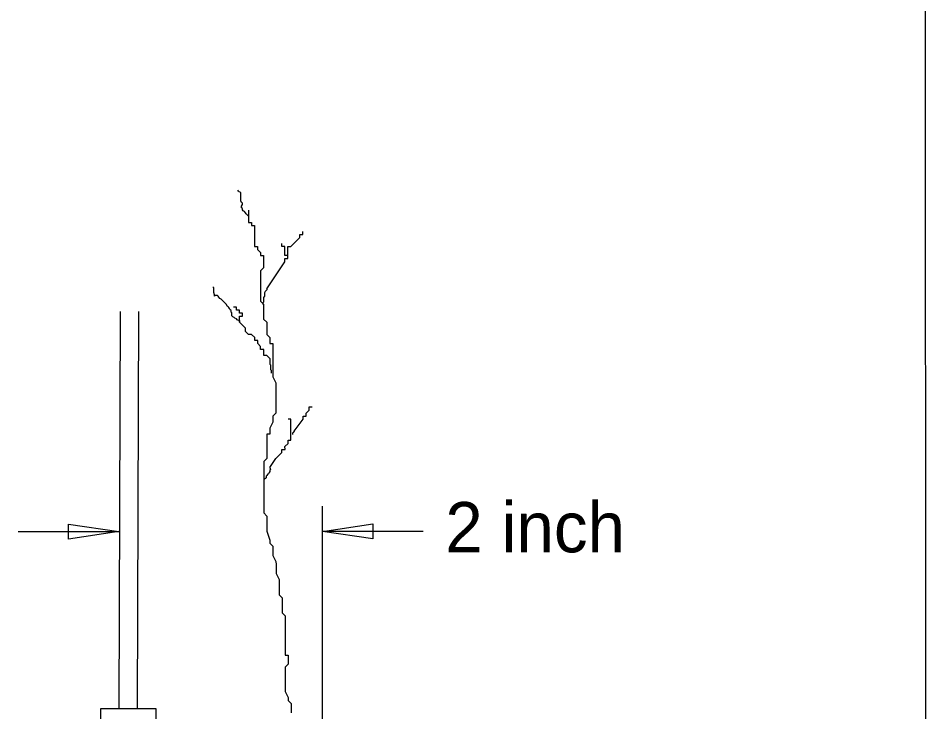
# Model space of a CAD drawing. Extents: x 1728110 to 1729925, y 1284214 to 1285339.
# Drawn here: x 1728940.3 to 1729065, y 1284983.6 to 1285078.4 of the extents above; entities that cross this region are included whole.
import ezdxf

# ---------------------------------------------------------------- set-up
doc = ezdxf.new("R2010")
doc.units = 0
doc.layers.add('Reforestation Detail CELL', color=7, linetype='Continuous')

msp = doc.modelspace()

# ---------------------------------------------------------------- linework, layer by layer
at = {"layer": 'Reforestation Detail CELL'}
for p, q in [((1729064.98, 1284278.34), (1729064.22, 1285292.11)), ((1728954.07, 1284984.03), (1728954.26, 1285038.31)), ((1728956.57, 1284984.02), (1728956.76, 1285038.3)), ((1728981.9, 1284980.49), (1728981.88, 1285011.68)), ((1728940.27, 1285008.2), (1728954.05, 1285008.21)), ((1728995.66, 1285008.24), (1728981.88, 1285008.23)), ((1728951.57, 1284981.19), (1728951.58, 1284984.03)), ((1728951.58, 1284984.03), (1728959.1, 1284984.01)), ((1728959.1, 1284984.01), (1728959.09, 1284981.17))]:
    msp.add_line(p, q, dxfattribs=at)
for points in [[(1728971.77, 1285051.34), (1728971.56, 1285051.59), (1728971.46, 1285051.7), (1728971.35, 1285051.8), (1728971.25, 1285052.01), (1728971.04, 1285052.11), (1728970.94, 1285052.21), (1728970.94, 1285052.42), (1728970.84, 1285052.52), (1728970.84, 1285052.73), (1728970.94, 1285052.94), (1728970.94, 1285053.15), (1728970.84, 1285053.25), (1728970.73, 1285053.46), (1728970.73, 1285053.77), (1728970.73, 1285053.97), (1728970.73, 1285054.18), (1728970.73, 1285054.39), (1728970.73, 1285054.59), (1728970.52, 1285054.7), (1728970.42, 1285054.8), (1728970.32, 1285054.9)], [(1728971.77, 1285052.17), (1728971.77, 1285051.34), (1728971.77, 1285050.93), (1728971.78, 1285050.51), (1728972.19, 1285050.51), (1728972.19, 1285050.1), (1728972.6, 1285050.1), (1728972.6, 1285049.69), (1728972.6, 1285049.27), (1728972.6, 1285048.86), (1728972.6, 1285048.44), (1728972.6, 1285048.03), (1728972.61, 1285047.61), (1728972.61, 1285047.2), (1728973.02, 1285047.2), (1728973.02, 1285046.79), (1728973.43, 1285046.37), (1728973.43, 1285045.96), (1728973.85, 1285045.96), (1728973.85, 1285045.55), (1728973.85, 1285045.13), (1728973.85, 1285044.72), (1728973.85, 1285044.3), (1728973.44, 1285043.89), (1728973.44, 1285043.47), (1728973.44, 1285043.06), (1728973.44, 1285042.65), (1728973.44, 1285042.23), (1728973.44, 1285041.82), (1728973.44, 1285041.4), (1728973.44, 1285040.99), (1728973.44, 1285040.57), (1728973.44, 1285040.16), (1728973.44, 1285039.75), (1728973.85, 1285039.33), (1728973.85, 1285038.92), (1728973.85, 1285038.51), (1728973.85, 1285038.09), (1728973.85, 1285037.67), (1728973.85, 1285037.26), (1728974.27, 1285036.85), (1728974.27, 1285036.43), (1728974.27, 1285036.02), (1728974.27, 1285035.61), (1728974.27, 1285035.19), (1728974.68, 1285034.78), (1728974.69, 1285033.95), (1728975.1, 1285033.95), (1728975.1, 1285033.54), (1728975.1, 1285033.12), (1728975.1, 1285032.71), (1728975.1, 1285032.29), (1728975.1, 1285031.46), (1728975.1, 1285030.64), (1728975.1, 1285029.39), (1728975.52, 1285028.57), (1728975.52, 1285028.15), (1728975.52, 1285027.74), (1728975.52, 1285027.32), (1728975.52, 1285026.91), (1728975.52, 1285026.49), (1728975.52, 1285026.08), (1728975.52, 1285025.67), (1728975.52, 1285025.25), (1728975.52, 1285024.84), (1728975.52, 1285024.42), (1728975.11, 1285024.01), (1728975.11, 1285023.18), (1728974.69, 1285022.35), (1728974.69, 1285021.94), (1728974.69, 1285021.52), (1728974.28, 1285021.52), (1728974.28, 1285021.11), (1728974.28, 1285020.7), (1728974.28, 1285020.28), (1728974.28, 1285019.87), (1728974.28, 1285019.45), (1728974.28, 1285019.04), (1728974.28, 1285018.62), (1728974.28, 1285018.21), (1728973.87, 1285017.8), (1728973.87, 1285017.38), (1728973.87, 1285016.97), (1728973.87, 1285016.55), (1728973.87, 1285016.14), (1728973.87, 1285015.73), (1728973.87, 1285015.31), (1728973.87, 1285014.9), (1728973.87, 1285014.48), (1728973.87, 1285013.65), (1728973.87, 1285013.24), (1728973.87, 1285012.83), (1728973.87, 1285012), (1728973.87, 1285011.58), (1728973.87, 1285011.17), (1728973.87, 1285010.76), (1728974.29, 1285010.34), (1728974.29, 1285009.93), (1728974.29, 1285009.51), (1728974.29, 1285009.1), (1728974.29, 1285008.27)], [(1728977.16, 1285045.55), (1728977.16, 1285046.79), (1728977.16, 1285047.2), (1728977.57, 1285047.2), (1728977.99, 1285047.62), (1728978.4, 1285048.03), (1728978.81, 1285048.45), (1728978.81, 1285048.86), (1728979.23, 1285048.86), (1728979.23, 1285049.28)], [(1728974.27, 1285041.4), (1728976.75, 1285045.13), (1728976.75, 1285045.55), (1728977.16, 1285045.55), (1728977.16, 1285045.96), (1728976.75, 1285045.96), (1728976.74, 1285046.37), (1728976.74, 1285046.79), (1728976.74, 1285047.2), (1728976.33, 1285047.2), (1728976.33, 1285047.62)], [(1728970.54, 1285036.85), (1728970.64, 1285036.99), (1728970.23, 1285037.2), (1728970.12, 1285037.3), (1728969.92, 1285037.41), (1728969.81, 1285037.51), (1728969.61, 1285037.61), (1728969.5, 1285037.72), (1728969.5, 1285037.92), (1728969.5, 1285038.13), (1728969.4, 1285038.23), (1728969.4, 1285038.44), (1728969.29, 1285038.54), (1728969.19, 1285038.75), (1728969.09, 1285038.85), (1728968.98, 1285038.96), (1728968.88, 1285039.06), (1728968.78, 1285039.27), (1728968.57, 1285039.48), (1728968.36, 1285039.68), (1728968.16, 1285039.89), (1728968.05, 1285039.99), (1728967.85, 1285040.1), (1728967.74, 1285040.3), (1728967.64, 1285040.41), (1728967.53, 1285040.51), (1728967.22, 1285040.51), (1728967.12, 1285040.41), (1728967.12, 1285040.61), (1728967.02, 1285040.92), (1728967.02, 1285041.13), (1728967.02, 1285041.34), (1728967.02, 1285041.55), (1728966.91, 1285041.65)], [(1728974.27, 1285041.4), (1728974.27, 1285041.26), (1728974.16, 1285041.16), (1728974.06, 1285041.05), (1728973.95, 1285040.85), (1728973.95, 1285040.64), (1728973.95, 1285040.43), (1728973.85, 1285040.22), (1728973.85, 1285040.02), (1728973.85, 1285039.81), (1728973.85, 1285039.6), (1728973.75, 1285039.5), (1728973.75, 1285039.29)], [(1728974.69, 1285031.88), (1728974.27, 1285032.29), (1728973.86, 1285032.29), (1728973.86, 1285032.71), (1728973.86, 1285033.12), (1728973.44, 1285033.12), (1728973.44, 1285033.53), (1728973.03, 1285033.95), (1728973.03, 1285034.36), (1728972.62, 1285034.36), (1728972.62, 1285034.78), (1728972.2, 1285035.19), (1728971.79, 1285035.19), (1728971.37, 1285035.6), (1728971.37, 1285036.02), (1728970.96, 1285036.43), (1728970.54, 1285036.85), (1728970.54, 1285037.26), (1728970.54, 1285037.67), (1728970.96, 1285037.67), (1728970.96, 1285038.09), (1728970.54, 1285038.09), (1728970.54, 1285038.5), (1728970.13, 1285038.5), (1728970.13, 1285038.92), (1728969.71, 1285038.92)], [(1728974.69, 1285031.88), (1728974.69, 1285031.32), (1728974.69, 1285031.11), (1728974.79, 1285031.01), (1728974.79, 1285030.8), (1728974.79, 1285030.6), (1728974.79, 1285030.39), (1728974.89, 1285030.29), (1728974.89, 1285030.08), (1728974.89, 1285029.87)], [(1728978.01, 1285021.94), (1728979.25, 1285023.6), (1728979.24, 1285024.01), (1728979.66, 1285024.01), (1728979.66, 1285024.43), (1728980.07, 1285024.84), (1728980.07, 1285025.26), (1728980.49, 1285025.26)], [(1728974.7, 1285016.97), (1728975.52, 1285018.21), (1728975.94, 1285018.63), (1728976.35, 1285019.04), (1728976.35, 1285019.45), (1728976.77, 1285019.45), (1728976.76, 1285019.87), (1728977.18, 1285020.28), (1728977.18, 1285020.7), (1728977.59, 1285020.7), (1728977.59, 1285021.11), (1728977.59, 1285021.53), (1728977.59, 1285021.94), (1728977.59, 1285022.36), (1728977.59, 1285022.77), (1728977.59, 1285023.18), (1728977.59, 1285023.6), (1728977.18, 1285023.6)], [(1728978.01, 1285021.94), (1728977.9, 1285021.78), (1728977.79, 1285021.67), (1728977.79, 1285021.47)], [(1728974.7, 1285016.97), (1728974.8, 1285016.72), (1728974.7, 1285016.62), (1728974.7, 1285016.41), (1728974.59, 1285016.31), (1728974.49, 1285016.1), (1728974.39, 1285016), (1728974.28, 1285015.89), (1728974.18, 1285015.79), (1728974.18, 1285015.58), (1728974.08, 1285015.48), (1728973.97, 1285015.37)], [(1728974.29, 1285008.27), (1728974.71, 1285007.03), (1728974.71, 1285006.61), (1728975.12, 1285006.2), (1728975.12, 1285005.37), (1728975.12, 1285004.96), (1728975.53, 1285004.13), (1728975.54, 1285003.72), (1728975.54, 1285002.89), (1728975.54, 1285002.47), (1728975.95, 1285001.65), (1728975.95, 1285000.82), (1728975.95, 1284999.99), (1728975.95, 1284999.57), (1728976.37, 1284999.16), (1728976.37, 1284998.33), (1728976.37, 1284997.92), (1728976.37, 1284997.5), (1728976.37, 1284997.09), (1728976.78, 1284996.68), (1728976.78, 1284996.26), (1728976.78, 1284995.85), (1728976.78, 1284995.43), (1728976.78, 1284995.02), (1728976.78, 1284994.61), (1728976.78, 1284994.19), (1728976.78, 1284993.78), (1728976.78, 1284993.36), (1728976.78, 1284992.95), (1728976.79, 1284992.53), (1728976.79, 1284992.12), (1728976.79, 1284991.71), (1728976.79, 1284991.29), (1728977.2, 1284991.29), (1728977.2, 1284990.88), (1728977.2, 1284990.46), (1728977.2, 1284990.05), (1728976.79, 1284989.64), (1728976.79, 1284989.22), (1728976.79, 1284988.81), (1728976.79, 1284988.39), (1728976.79, 1284987.56), (1728976.79, 1284987.15), (1728976.79, 1284986.32), (1728977.2, 1284985.49), (1728977.2, 1284985.08), (1728977.62, 1284984.67), (1728977.62, 1284983.84), (1728977.62, 1284983.42)]]:
    msp.add_lwpolyline(points, dxfattribs=at)
for points in [[(1728947.16, 1285009.24), (1728954.05, 1285008.21), (1728947.16, 1285007.17)], [(1728988.77, 1285007.2), (1728981.88, 1285008.23), (1728988.77, 1285009.27)]]:
    msp.add_lwpolyline(points, close=True, dxfattribs=at)

# ---------------------------------------------------------------- texts
msp.add_text('2 inch', height=6.89, rotation=0.0429, dxfattribs=at).set_placement((1728998.7, 1285005.36))

doc.saveas('drawing.dxf')
